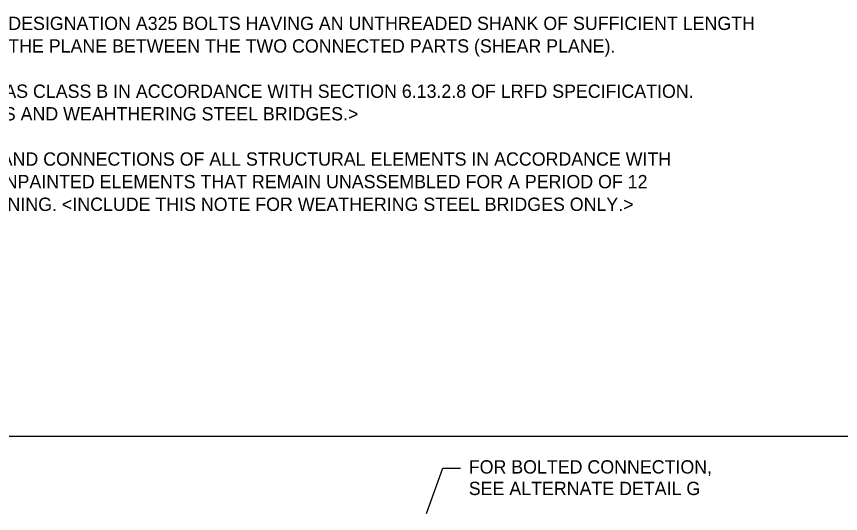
# Model space of a CAD drawing. Extents: x 634656 to 641360, y 298715 to 301183.
# Drawn here: x 640317.7 to 640503.5, y 299990 to 300102 of the extents above; entities that cross this region are included whole.
import ezdxf

# ---------------------------------------------------------------- set-up
doc = ezdxf.new("R2010")
doc.units = 0
doc.layers.add('1', color=7, linetype='Continuous')
doc.layers.add('2', color=7, linetype='Continuous')

msp = doc.modelspace()

# ---------------------------------------------------------------- linework, layer by layer
at = {"layer": '2'}
for p, q in [((640243.86, 300007.39), (641029.86, 300007.39)), ((640410.18, 299989.97), (640413.86, 300000.22)), ((640413.86, 300000.22), (640417.85, 300000.22))]:
    msp.add_line(p, q, dxfattribs=at)

# ---------------------------------------------------------------- texts
at = {"layer": '1'}
for s, height, p in [('USE <SPECIFY BOLT SIZE> DIAMETER ASTM DESIGNATION A325 BOLTS HAVING AN UNTHREADED SHANK OF SUFFICIENT LENGTH', 2.99987, (640227.84, 300098.99)), ('TO NOT ALLOW ANY THREADS TO EXIST INT THE PLANE BETWEEN THE TWO CONNECTED PARTS (SHEAR PLANE).', 2.9999, (640227.84, 300093.89)), ('FURNISH PAINT THAT HAS BEEN QUALIFIED AS CLASS B IN ACCORDANCE WITH SECTION 6.13.2.8 OF LRFD SPECIFICATION.', 2.99987, (640227.84, 300083.69)), ('<INCLUDE THIS NOTE FOR PAINTED BRIDGES AND WEAHTHERING STEEL BRIDGES.>', 2.9999, (640227.84, 300078.6)), ('    f)  BLAST CLEAN THE FAYING SURFACES OF SPLICES AND CONNECTIONS OF ALL STRUCTURAL ELEMENTS IN ACCORDANCE WITH', 2.99987, (640203.84, 300068.4)), ('          PUBLICATION 408 SECTION 1060.3(B)3.  REBLAST UNPAINTED ELEMENTS THAT REMAIN UNASSEMBLED FOR A PERIOD OF 12', 2.99987, (640203.84, 300063.3)), ('          MONTHS OR MORE FOLLOWING THE INTITIAL CLEANING. <INCLUDE THIS NOTE FOR WEATHERING STEEL BRIDGES ONLY.>', 2.99987, (640203.84, 300058.2)), ('FOR BOLTED CONNECTION,', 3, (640419.68, 299998.99)), ('SEE ALTERNATE DETAIL G', 3, (640419.68, 299994.13))]:
    msp.add_text(s, height=height, dxfattribs=at).set_placement(p)

doc.saveas('drawing.dxf')
